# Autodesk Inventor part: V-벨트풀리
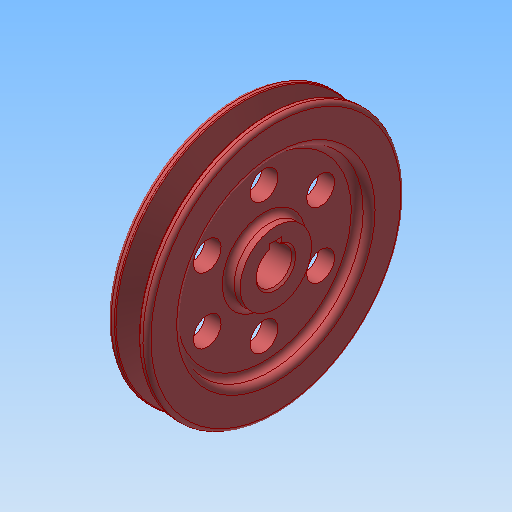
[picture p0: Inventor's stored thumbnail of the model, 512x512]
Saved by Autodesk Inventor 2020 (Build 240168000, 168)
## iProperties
Created: 2010-03
Part Number: V-벨트풀리
Document SubType Name: Modeling
Designer: Administrator
Density: 1 g/cm^3
Material: 스테인리스강
Appearance: 기본값(2)
Author: Administrator
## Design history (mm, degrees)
sketch "스케치1"
  geometry: L1 (-10, 0)-(10, 0); L2 (10, 0)-(10, 65); L3 (-10, 65)-(-10, 0); L4 (10, 19)-(10, 0); L5 (-10, 65)-(-6.062, 65); L6 (-6.062, 65)-(-2.001, 52.5); L7 (2.001, 52.5)-(6.062, 65); L8 (6.062, 65)-(10, 65); L9 (-2.001, 52.5)-(2.001, 52.5); L10 (-10, 47)-(-4, 47); L11 (-4, 47)-(-4, 18); L12 (-4, 18)-(-10, 18); L13 (-10, 18)-(-10, 47); L14 (10, 47)-(4, 47); L15 (4, 47)-(4, 18); L16 (4, 18)-(10, 18); L17 (10, 18)-(10, 47); 5 further points
  constraints: 34 end point, 6 collinear, 6 horizontal, 5 parallel, 4 point on line, 3 perpendicular, 2 midpoint, 1 coincident, 1 horizontal alignment, 1 vertical alignment
  dimensions: "d0" = 121 diameter of point (-4.6, 60.5) L1; "d1" = 4.5 distance from line of L5 point (-4.6, 60.5); "d2" = 8 distance from line of L9 point (-4.6, 60.5); "d3" = 9.2 distance of point (-4.6, 60.5) point (4.6, 60.5); "d4" = 36 deg angle of L7 L6; "d5" = 10 distance from line of point (0, 52.5) L3; "d8" = 6 distance of L14.start L14.end; "d10" = 29 distance of L14.end L15.end; "d29" = 36 diameter of L16 L1
revolve "회전1" sketch "스케치1" stored, may be unused: angle "d11" = 90 deg
fillet "모깎기1" dims "d12" = 2, "d13" = 1, "d14" = 0.5
fillet "모깎기2" dims "d15" = 3
sketch "스케치2"
  geometry: L1 (-3, 8.485)-(3, 8.485); L2 (3, 8.485)-(3, 11.8); L3 (3, 11.8)-(-3, 11.8); L4 (-3, 11.8)-(-3, 8.485); C1 r 18 at (0, 0) reference; A1 r 9 centre (0, 0) between (-3, 8.485) and (3, 8.485)
  constraints: 8 end point, 2 parallel, 2 point on circle, 1 centre point, 1 concentric, 1 horizontal, 1 perpendicular
  dimensions: "d16" = 18 diameter of A1; "d19" = 2.8 distance edge to line of A1 L3; "d20" = 6 distance of L2.end L3.end
extrude "돌출1" cut sketch "스케치2" extent not by distance; stored distance "d17" = 10; taper "d18" = 0 deg
chamfer "모따기1" distance "d30" = 1; stored, may be unused: second distance "d31" = 2, angle "d32" = 45 deg
sketch "스케치4" dims "d33" = 66
  geometry: C1 r 7 at (0, 33); 2 further points
  constraints: 2 vertical alignment, 1 centre point, 1 coincident, 2 other
  dimensions: "d34" = 14 diameter of C1
extrude "돌출2" cut sketch "스케치4" extent not by distance; stored distance "d35" = 10; taper "d36" = 0 deg
node "솔리드1"
pattern_circular "원형 패턴1" dims angle "d38" = 360 deg
